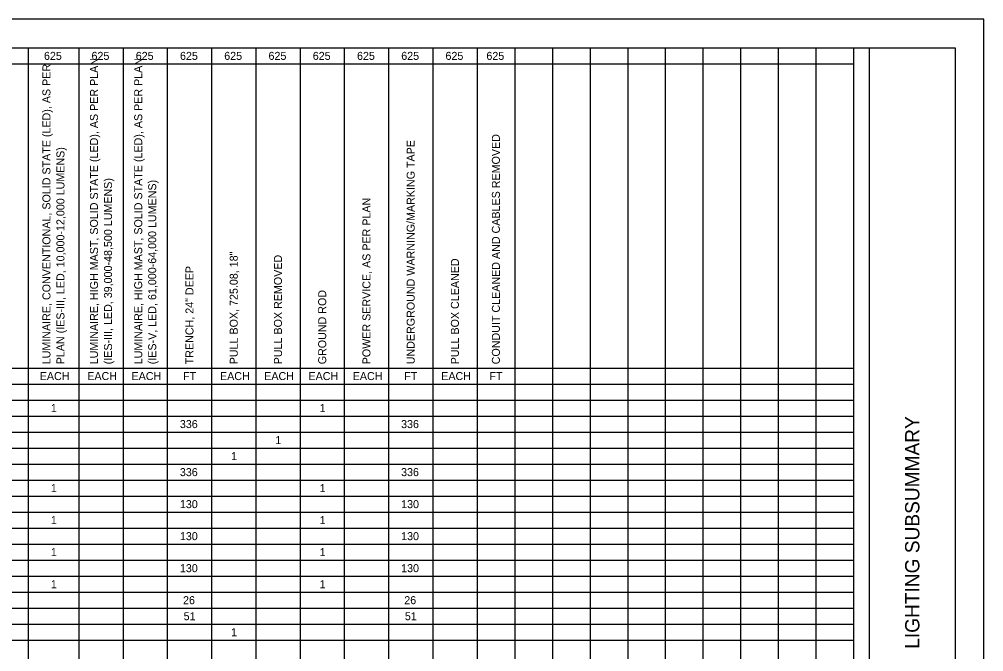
# Model space of a CAD drawing. Extents: x 0 to 34, y 0 to 22.
# Drawn here: x 17.13 to 34, y 10.94 to 22 of the extents above; entities that cross this region are included whole.
import ezdxf

# ---------------------------------------------------------------- set-up
doc = ezdxf.new("R2010")
doc.units = 0
for name, color, linetype in [('SH_Border', 7, 'Continuous'), ('SH_Cut_Line', 7, 'Continuous'), ('SH_Data', 7, 'Continuous'), ('SH_Text', 7, 'Continuous')]:
    doc.layers.add(name, color=color, linetype=linetype)

msp = doc.modelspace()

# ---------------------------------------------------------------- linework, layer by layer
at = {"layer": 'SH_Border'}
msp.add_line((32, 0.5), (32, 21.5), dxfattribs=at)
msp.add_lwpolyline([(1.5, 21.5), (33.5, 21.5), (33.5, 0.5), (1.5, 0.5)], close=True, dxfattribs=at)
at = {"layer": 'SH_Cut_Line'}
msp.add_lwpolyline([(0, 0), (34, 0), (34, 22), (0, 22)], close=True, dxfattribs=at)
at = {"layer": 'SH_Text'}
for p, q in [((1.5, 21.5), (31.724, 21.5)), ((17.279, 21.5), (17.279, 0.5)), ((18.168, 21.5), (18.168, 0.5)), ((18.942, 21.5), (18.942, 0.5)), ((19.716, 21.5), (19.716, 0.5)), ((20.491, 21.5), (20.491, 0.5)), ((21.265, 21.5), (21.265, 0.5)), ((22.039, 21.5), (22.039, 0.5)), ((22.813, 21.5), (22.813, 0.5)), ((23.587, 21.5), (23.587, 0.5)), ((24.361, 21.5), (24.361, 0.5)), ((25.135, 21.5), (25.135, 0.5)), ((25.794, 21.5), (25.794, 0.5)), ((26.453, 21.5), (26.453, 0.5)), ((27.112, 21.5), (27.112, 0.5)), ((27.771, 21.5), (27.771, 0.5)), ((28.429, 21.5), (28.429, 0.5)), ((29.088, 21.5), (29.088, 0.5)), ((29.747, 21.5), (29.747, 0.5)), ((30.406, 21.5), (30.406, 0.5)), ((31.065, 21.5), (31.065, 0.5)), ((31.724, 21.5), (31.724, 0.5)), ((8.451, 21.22), (31.724, 21.22)), ((8.451, 15.9), (31.724, 15.9)), ((1.5, 15.62), (31.724, 15.62)), ((1.5, 15.34), (31.724, 15.34)), ((1.5, 15.06), (31.724, 15.06)), ((1.5, 14.78), (31.724, 14.78)), ((1.5, 14.5), (31.724, 14.5)), ((1.5, 14.22), (31.724, 14.22)), ((1.5, 13.94), (31.724, 13.94)), ((1.5, 13.66), (31.724, 13.66)), ((1.5, 13.38), (31.724, 13.38)), ((1.5, 13.1), (31.724, 13.1)), ((1.5, 12.82), (31.724, 12.82)), ((1.5, 12.54), (31.724, 12.54)), ((1.5, 12.26), (31.724, 12.26)), ((1.5, 11.98), (31.724, 11.98)), ((1.5, 11.7), (31.724, 11.7)), ((1.5, 11.42), (31.724, 11.42)), ((1.5, 11.14), (31.724, 11.14))]:
    msp.add_line(p, q, dxfattribs=at)

# ---------------------------------------------------------------- texts
at = {"layer": 'SH_Data'}
msp.add_text('LIGHTING SUBSUMMARY', height=0.25, rotation=90, dxfattribs=at).set_placement((32.875, 10.99))
at = {"layer": 'SH_Text'}
for s, p in [('625', (17.558, 21.29)), ('625', (18.39, 21.29)), ('625', (19.164, 21.29)), ('625', (19.938, 21.29)), ('625', (20.712, 21.29)), ('625', (21.487, 21.29)), ('625', (22.261, 21.29)), ('625', (23.035, 21.29)), ('625', (23.809, 21.29)), ('625', (24.583, 21.29)), ('625', (25.299, 21.29)), ('EACH', (17.484, 15.69)), ('EACH', (18.316, 15.69)), ('EACH', (19.09, 15.69)), ('FT', (19.991, 15.69)), ('EACH', (20.638, 15.69)), ('EACH', (21.412, 15.69)), ('EACH', (22.186, 15.69)), ('EACH', (22.96, 15.69)), ('FT', (23.862, 15.69)), ('EACH', (24.509, 15.69)), ('FT', (25.353, 15.69)), ('1', (17.678, 15.13)), ('1', (22.38, 15.13)), ('336', (19.936, 14.85)), ('336', (23.806, 14.85)), ('1', (21.606, 14.57)), ('1', (20.832, 14.29)), ('336', (19.936, 14.01)), ('336', (23.806, 14.01)), ('1', (17.678, 13.73)), ('1', (22.38, 13.73)), ('130', (19.936, 13.45)), ('130', (23.807, 13.45)), ('1', (17.678, 13.17)), ('1', (22.38, 13.17)), ('130', (19.936, 12.89)), ('130', (23.807, 12.89)), ('1', (17.678, 12.61)), ('1', (22.38, 12.61)), ('130', (19.936, 12.33)), ('130', (23.807, 12.33)), ('1', (17.678, 12.05)), ('1', (22.38, 12.05)), ('26', (19.991, 11.77)), ('26', (23.862, 11.77)), ('51', (20.002, 11.49)), ('51', (23.872, 11.49)), ('1', (20.832, 11.21))]:
    msp.add_text(s, height=0.14, dxfattribs=at).set_placement(p)
for s, p in [('LUMINAIRE, HIGH MAST, SOLID STATE (LED), AS PER PLAN ', (18.503, 15.966)), ('LUMINAIRE, HIGH MAST, SOLID STATE (LED), AS PER PLAN ', (19.277, 15.966)), ('LUMINAIRE, CONVENTIONAL, SOLID STATE (LED), AS PER ', (17.671, 15.966)), ('CONDUIT CLEANED AND CABLES REMOVED', (25.535, 15.966)), ('PLAN (IES-III, LED, 10,000-12,000 LUMENS)', (17.916, 15.966)), ('UNDERGROUND WARNING/MARKING TAPE', (24.044, 15.966)), ('(IES-III, LED, 39,000-48,500 LUMENS)', (18.748, 15.966)), ('(IES-V, LED, 61,000-64,000 LUMENS)', (19.522, 15.966)), ('POWER SERVICE, AS PER PLAN', (23.27, 15.966)), ('PULL BOX, 725.08, 18"', (20.948, 15.966)), ('PULL BOX REMOVED', (21.722, 15.966)), ('PULL BOX CLEANED', (24.818, 15.966)), ('TRENCH, 24" DEEP', (20.174, 15.966)), ('GROUND ROD', (22.496, 15.966))]:
    msp.add_text(s, height=0.14, rotation=90, dxfattribs=at).set_placement(p)

doc.saveas('drawing.dxf')
